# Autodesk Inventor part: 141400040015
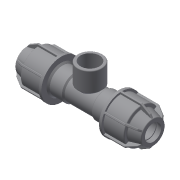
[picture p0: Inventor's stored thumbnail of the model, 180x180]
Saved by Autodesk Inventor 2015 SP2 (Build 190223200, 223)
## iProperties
Created: 2017-08
Part Number: 141400040015
Material: Generic
Description: PLASSON L.14 TEE FEMALE ADAPTOR (SILVER) 40 x 1.1/2" x 40
Document SubType Name: Modeling
Designer: KIM
Density: 1 g/cm^3
Appearance: Default
Author: KIM
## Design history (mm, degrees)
derived "141400.ipt"
feature "Solid1::141400.ipt"
feature "Solid2::141400.ipt"
tag "TaggingFeature1"
body "Solid1"
other parameters: "d2" = 62, "d4" = 15 deg, "d5" = 40.92, "d6" = 13.5036, "d10" = 73, "d16" = 40.8, "d17" = 3.1, "d22" = 64, "d24" = 3.1, "d25" = 65.7, "d26" = 54.75, "d27" = 3.1, "d28" = 135 deg, "d29" = 1.86, "d31" = 2, "d46" = 150 deg, "d49" = 3.65, "d50" = 0, "d58" = 1.2, "d61" = 360 deg, "d63" = 36, "d64" = 86.5, "d80" = 57.6, "d81" = 3.2, "d84" = 3.1, "d94" = 68, "d95" = 44.845, "d96" = 58.2985, "d97" = 25, "d98" = 36, "d99" = 40.80895, "d100" = 135 deg, "d108" = 2, "d111" = 0, "G_" = 44.845, "E_" = 73, "H_" = 173, "l_" = 62, "l_2" = 25, "A_" = 68
